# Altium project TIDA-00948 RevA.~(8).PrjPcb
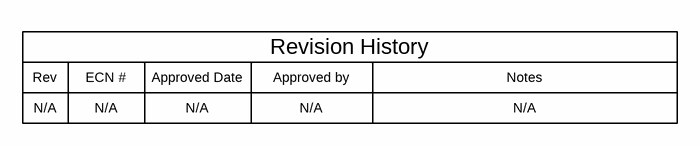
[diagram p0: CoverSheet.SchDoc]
TID: TIDA-00948; TechSupport: http://www.ti.com/support; SCH_Rev: E1; PRJ_Title: High Efficiency DCDC Module with TO247 Form Factor; PRJ_Number: TIDA-00948; PRJ_Engineer: Jason Tao; PRJ_Customer: Public Release; PCB_Rev: E1; PCB_Layout: Jason; EVM_Orderable: N/A; CopyrightYear: 2016
3 sheets, 34 parts. Net scope: global (net labels, ports and power ports of the same name join across sheets).
Board file: TIDA-00948 RevA03.PcbDoc
Sheets:
  CoverSheet.SchDoc
  TIDA-00948 RevA01.SchDoc
  TID_Hardware.SchDoc

## Sheet CoverSheet.SchDoc
size 431 x 279 mm; Date: Not shown in title block; ApprovedBy: Not shown in title block; CheckedBy: Not shown in title block; Author: Not shown in title block; CompanyName: Not shown in title block; Engineer: Not shown in title block; Organization: Not shown in title block; Address1: Not shown in title block; Address2: Not shown in title block; Address3: Not shown in title block; Address4: Not shown in title block; DocumentNumber: 1; Revision: Use project parameter SCH_Rev; SheetNumber: 1; SheetTotal: 3; PageSetup: Record=PageOptions¦CenterHorizontal=True¦CenterVertical=True¦PrintScale=1.00¦XCorrection=1.00¦YCorrection=1.00¦PrintKind=0¦BorderSize=5000000¦LeftOffset=0¦BottomOffset=0¦Orientation=2¦PaperLength=1000¦PaperWidth=1000¦Scale=100¦PaperSource=15¦PrintQuality=600¦MediaType=1¦DitherType=10¦PaperKind=Letter¦PrintScaleMode=1

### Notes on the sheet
- Rev
- N/A
- ECN #
- Approved Date
- Approved by
- Revision History
- Notes

## Sheet TIDA-00948 RevA01.SchDoc
size 431 x 279 mm; Date: Not shown in title block; ApprovedBy: Not shown in title block; CheckedBy: Not shown in title block; Author: Not shown in title block; CompanyName: Not shown in title block; Engineer: Not shown in title block; Organization: Not shown in title block; Address1: Not shown in title block; Address2: Not shown in title block; Address3: Not shown in title block; Address4: Not shown in title block; DocumentNumber: 1; Revision: Use project parameter SCH_Rev; SheetNumber: 2; SheetTotal: 3; PageSetup: Record=PageOptions¦CenterHorizontal=True¦CenterVertical=True¦PrintScale=1.00¦XCorrection=1.00¦YCorrection=1.00¦PrintKind=0¦BorderSize=5000000¦LeftOffset=0¦BottomOffset=0¦Orientation=2¦PaperLength=1000¦PaperWidth=1000¦Scale=100¦PaperSource=15¦PrintQuality=600¦MediaType=1¦DitherType=10¦PaperKind=Letter¦PrintScaleMode=1
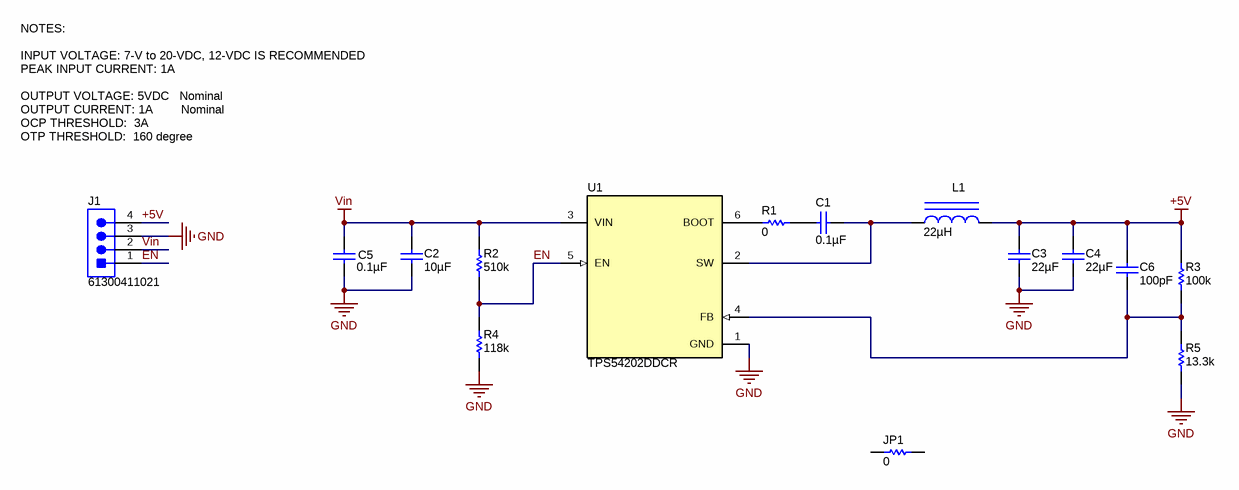
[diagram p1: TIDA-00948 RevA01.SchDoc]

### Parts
C1  ValueDisplayed: 0.1µF  [0805_HV]  (hidden comment: GRM21BR71E104KA01L)
C2  ValueDisplayed: 10µF  [1206]  (hidden comment: GRM31CR71E106KA12L)
C3  ValueDisplayed: 22µF  [1206_190]  (hidden comment: GCM31CR71A226KE02)
C4  ValueDisplayed: 22µF  [1206_190]  (hidden comment: GCM31CR71A226KE02)
C5  ValueDisplayed: 0.1µF  [0603]  (hidden comment: GRM188R71E104KA01D)
C6  ValueDisplayed: 100pF  [C/0805/SMT1]  (hidden comment: 06033C101KAT2A)
J1  61300411021  [Wurth_61300411021]
JP1  ValueDisplayed: 0  [JUMP-5]  (hidden comment: CRCW0603100KFKEA)
L1  ValueDisplayed: 22µH  [LPS8045B]  (hidden comment: THPC6045MF-220M)
R1  ValueDisplayed: 0  [0603]  (hidden comment: CRCW06030000Z0EA)
R2  ValueDisplayed: 510k  [0603]  (hidden comment: CRCW0603510KJNEA)
R3  ValueDisplayed: 100k  [R/0805/SMT1]  (hidden comment: CRCW0603100KFKEA)
R4  ValueDisplayed: 118k  [0603]  (hidden comment: CRCW0603118KFKEA)
R5  ValueDisplayed: 13.3k  [0603]  (hidden comment: CRCW060313K3FKEA)
U1  TPS54202DDCR  [DDC0006A_N]

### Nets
+5V: C3.1 C4.1 C6.1 J1.4 L1.2 R3.2
GND: C2.2 C3.2 C4.2 C5.2 J1.3 R4.1 R5.1 U1.1(GND)
Vin: C2.1 C5.1 J1.2 R2.2 U1.3(VIN)
EN: J1.1 R2.1 R4.2 U1.5(EN)
NetC1_1: C1.1 L1.1 U1.2(SW)
NetC1_2: C1.2 R1.2
NetC6_2: C6.2 R3.1 R5.2 U1.4(FB)
NetR1_1: R1.1 U1.6(BOOT)

Not connected (* = marked no-connect by the designer): JP1 1 2

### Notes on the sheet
- NOTES:
  INPUT VOLTAGE: 7-V to 20-VDC, 12-VDC IS RECOMMENDED
  PEAK INPUT CURRENT: 1A
  OUTPUT VOLTAGE: 5VDC   Nominal
  OUTPUT CURRENT: 1A        Nominal
  OCP THRESHOLD:  3A
  OTP THRESHOLD:  160 degree

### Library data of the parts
C1 = GRM21BR71E104KA01L: CAP, CERM, 0.1 µF, 25 V, +/- 10%, X7R, 0805; Manufacturer: MuRata; Polarized: N; CompType: Capacitor; Value: 0.1uF; U/M: EA; Cap_F: 0.0000001; Tolerance_%: 10; Value1: Unknown; VDC_V: 25; Value2: 25V; TaMin_C: -55; TaMax_C: 125; Cap_Case: 0805; AEC Category: Q200
C2 = GRM31CR71E106KA12L: CAP, CERM, 10 µF, 25 V, +/- 10%, X7R, 1206; Manufacturer: MuRata; Polarized: N; CompType: Capacitor; Value: 10uF; U/M: EA; Cap_F: 0.00001; Tolerance_%: 10; Value1: Unknown; VDC_V: 25; Value2: 25V; TaMin_C: -55; TaMax_C: 125; Cap_Case: 2220; AEC Category: Q200
C3 C4 = GCM31CR71A226KE02: CAP, CERM, 22 µF, 10 V, +/- 10%, X7R, AEC-Q200 Grade 1, 1206_190; Manufacturer: MuRata; Polarized: N; CompType: Capacitor; Value: 22uF; U/M: EA; Cap_F: 0.000022; Tolerance_%: 10; Value1: Unknown; Value2: 10V; TaMin_C: -55; TaMax_C: 125; Cap_Case: 1206; AEC Category: Q200; AEC Qualified: Y; AEC Grade: 1
C5 = GRM188R71E104KA01D: CAP, CERM, 0.1 µF, 25 V, +/- 10%, X7R, 0603; Manufacturer: MuRata; Polarized: N; CompType: Capacitor; Value: 0.1uF; U/M: EA; Cap_F: 0.0000001; Tolerance_%: 10; Value1: Unknown; VDC_V: 25; Value2: 25V; TaMin_C: -55; TaMax_C: 125; AEC Category: Q200
C6 = 06033C101KAT2A: CAP, CERM, 100 pF, 25 V, +/- 10%, X7R, 0603; Manufacturer: AVX; Polarized: N; CompType: Capacitor; Value: 100pF; U/M: EA; Cap_F: 0.0000000001; Tolerance_%: 10; Value1: Unknown; VDC_V: 25; Value2: 25V; TaMin_C: -55; TaMax_C: 125; Cap_Case: 0603; AEC Category: Q200
J1 = 61300411021: Header, 2.54 mm, 4x1, Gold, R/A, TH; Manufacturer: Wurth Elektronik; SymbolCreator: a0412235; Pitch_mm: 2.54; Gender: Male; Shrouded: N; Row_Count: 1
JP1 R3 = CRCW0603100KFKEA: RES, 100 k, 1%, 0.1 W, 0603; Manufacturer: Vishay-Dale; CompType: Resistor; Value: 100k; Res_ohm: 100000; Tolerance_%: 1; Power_W: 0.1; Value2: 0.1W; VDC_V: 75; TempCo: 100 ppm/C; EIA_Code: E96; U/M: EA; AEC Category: Q200
L1 = LPS8045B-333MRB: Inductor, Shielded, Ferrite, 22 µH, 3.3 A, SMD; Manufacturer: Coilcraft; Value: 33uH; Ind_H: 33.0E-6; Imax_A: 1.2; Irms: 1.2A @ 20C rise; Isat: 1.8A @ 10% inductance drop; DCR_ohm: 0.121; Value1: 0.121 ohm; Value2: 1.2A; AEC Category: Q200; AEC Qualified: N
R1 = CRCW06030000Z0EA: RES, 0, 5%, 0.1 W, 0603; Manufacturer: Vishay-Dale; CompType: Resistor; Value: 0; Value_Code: 0000; Tolerance_%: 5; Power_W: 0.1; Value2: 0.1W; VDC_V: 75; TempCo: 200 ppm/C; EIA_Code: E24; U/M: EA; AEC Category: Q200
R2 = CRCW0603510KJNEA: RES, 510 k, 5%, 0.1 W, 0603; Manufacturer: Vishay-Dale; CompType: Resistor; Value: 510k; Res_ohm: 510000; Tolerance_%: 5; Power_W: 0.1; Value2: 0.1W; VDC_V: 75; TempCo: 200 ppm/C; EIA_Code: E24; U/M: EA; AEC Category: Q200
R4 = CRCW0603118KFKEA: RES, 118 k, 1%, 0.1 W, 0603; Manufacturer: Vishay-Dale; CompType: Resistor; Value: 118k; Res_ohm: 118000; Tolerance_%: 1; Power_W: 0.1; Value2: 0.1W; VDC_V: 75; TempCo: 100 ppm/C; EIA_Code: E96; U/M: EA; AEC Category: Q200
R5 = CRCW060313K3FKEA: RES, 13.3 k, 1%, 0.1 W, 0603; Manufacturer: Vishay-Dale; CompType: Resistor; Value: 13.3k; Res_ohm: 13300; Value_Code: 13k3; Tolerance_%: 1; Power_W: 0.1; Value2: 0.1W; VDC_V: 75; TempCo: 100 ppm/C; EIA_Code: E96; U/M: EA; AEC Category: Q200
U1 = TPS54202DDCR: 4.5-V TO 28-V INPUT, 2-A OUTPUT, EMI FRIENDLY SYNCHRONUOUS STEP-DOWN CONVERTOR, DDC0006A; Alternate PartNumber: TPS54202DDCT; Manufacturer: Texas Instruments; SymbolCreator: a0411947; CompType: IC; U/M: EA

## Sheet TID_Hardware.SchDoc
size 431 x 279 mm; Date: Not shown in title block; ApprovedBy: Not shown in title block; CheckedBy: Not shown in title block; Author: Not shown in title block; CompanyName: Not shown in title block; Engineer: Not shown in title block; Organization: Not shown in title block; Address1: Not shown in title block; Address2: Not shown in title block; Address3: Not shown in title block; Address4: Not shown in title block; DocumentNumber: 1; Revision: Use project parameter SCH_Rev; SheetNumber: 3; SheetTotal: 3; PageSetup: Record=PageOptions¦CenterHorizontal=True¦CenterVertical=True¦PrintScale=1.00¦XCorrection=1.00¦YCorrection=1.00¦PrintKind=0¦BorderSize=5000000¦LeftOffset=0¦BottomOffset=0¦Orientation=2¦PaperLength=1000¦PaperWidth=1000¦Scale=100¦PaperSource=15¦PrintQuality=600¦MediaType=1¦DitherType=10¦PaperKind=Letter¦PrintScaleMode=1
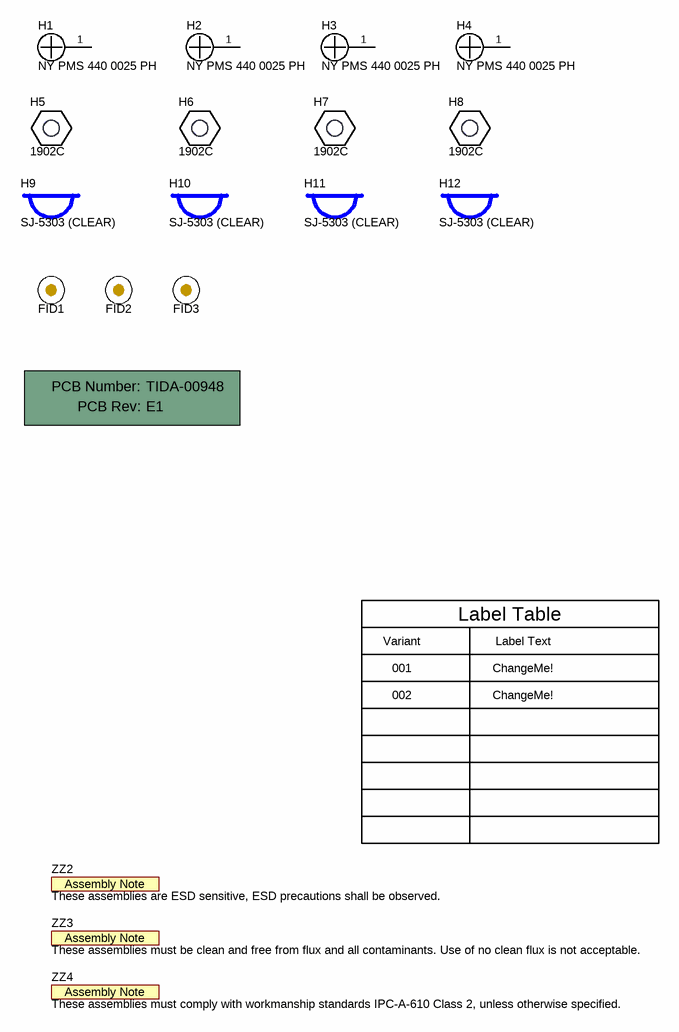
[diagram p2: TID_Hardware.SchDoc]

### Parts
!PCB  Printed Circuit Board  (value not drawn)  (mechanical)
FID1  Fiducial  [Fiducial10-20]  (value not drawn)
FID2  Fiducial  [Fiducial10-20]  (value not drawn)
FID3  Fiducial  [Fiducial10-20]  (value not drawn)
H1  NY PMS 440 0025 PH  [NY PMS 440 0025 PH]
H2  NY PMS 440 0025 PH  [NY PMS 440 0025 PH]
H3  NY PMS 440 0025 PH  [NY PMS 440 0025 PH]
H4  NY PMS 440 0025 PH  [NY PMS 440 0025 PH]
H5  1902C  [Keystone_1902C]
H6  1902C  [Keystone_1902C]
H7  1902C  [Keystone_1902C]
H8  1902C  [Keystone_1902C]
H9  SJ-5303 (CLEAR)  [Bumpon_SJ5003Transparent]
H10  SJ-5303 (CLEAR)  [Bumpon_SJ5003Transparent]
H11  SJ-5303 (CLEAR)  [Bumpon_SJ5003Transparent]
H12  SJ-5303 (CLEAR)  [Bumpon_SJ5003Transparent]
ZZ2  These assemblies are ESD sensitive, ESD precautions shall be observed.  [AssemblyNote]  (no BOM)
ZZ3  These assemblies must be clean and free from flux and all contaminants. Use of no clean flux is not acceptable.  [AssemblyNote]  (no BOM)
ZZ4  These assemblies must comply with workmanship standards IPC-A-610 Class 2, unless otherwise specified.  [AssemblyNote]  (no BOM)

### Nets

Not connected (* = marked no-connect by the designer): H1 1; H2 1; H3 1; H4 1

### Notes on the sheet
- Variant
- Label Table
- Label Text
- 001
- 002
- ChangeMe!

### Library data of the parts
!PCB = PCB: Manufacturer: Any; PartNumber: TIDA-00948; SymbolCreator: a0412235
FID1-FID3 = Fiducial: Fiducial mark.  There is nothing to buy or mount.; SymbolCreator: codlsc
H1-H4 = NY PMS 440 0025 PH: Machine Screw, Round, #4-40 x 1/4, Nylon, Philips panhead; Manufacturer: B&F Fastener Supply; CompType: Hardware; SymbolCreator: codlsc; U/M: EA
H5-H8 = 1902C: Standoff, Hex, 0.5"L #4-40 Nylon; Manufacturer: Keystone; CompType: Hardware
H9-H12 = SJ-5303 (CLEAR): Bumpon, Hemisphere, 0.44 X 0.20, Clear; Manufacturer: 3M; SymbolCreator: a0412235
ZZ2-ZZ4 = AssemblyNote: SymbolCreator: codlsc

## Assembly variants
001: not fitted FID1 FID2 FID3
